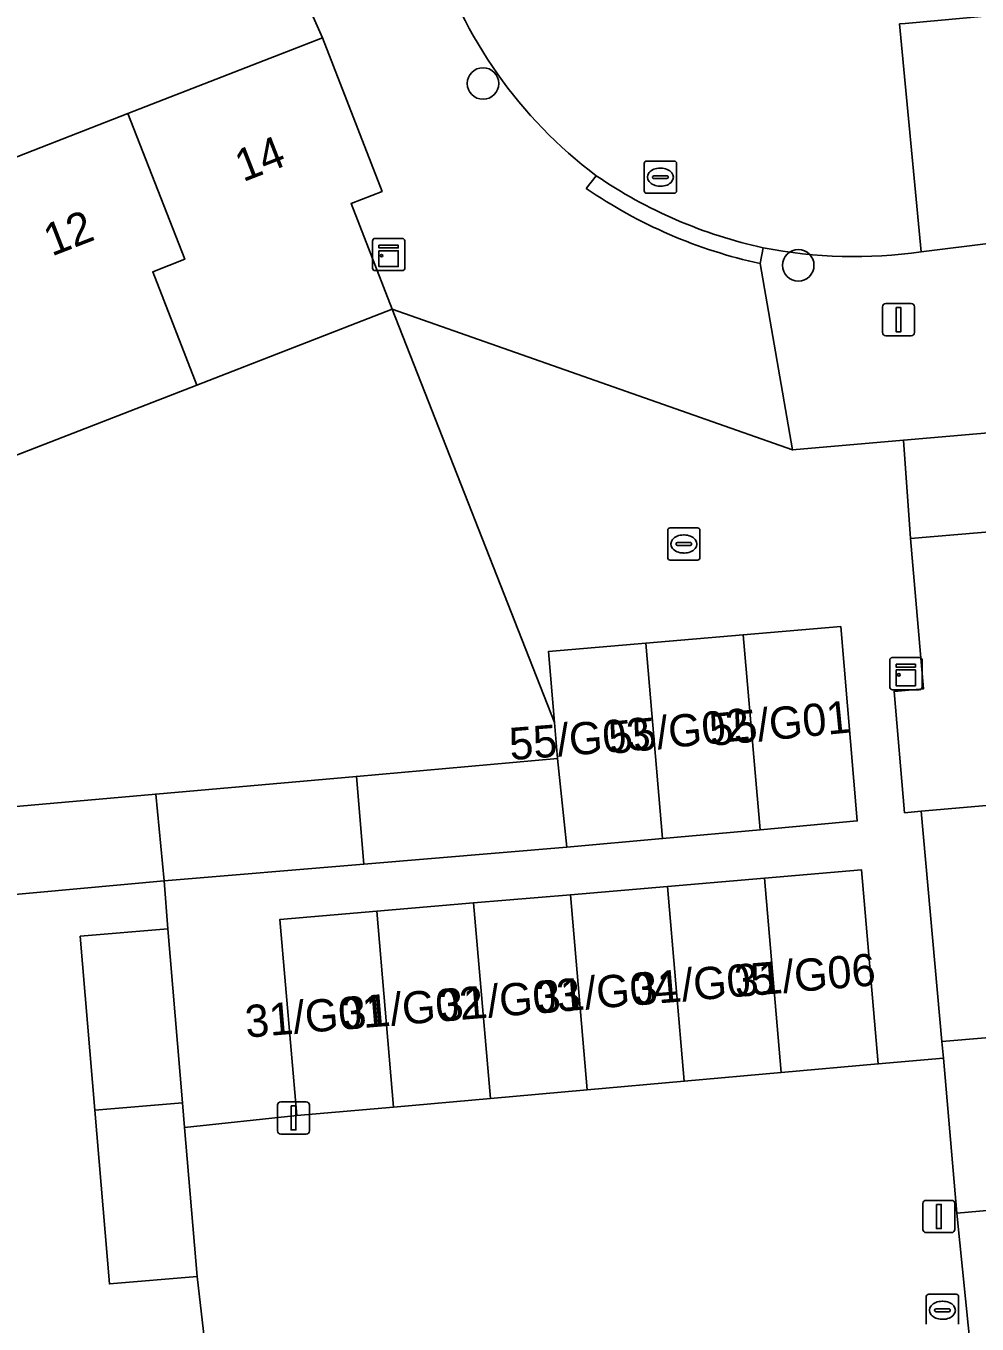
# Model space of a CAD drawing. Extents: x 162989 to 165008, y 383432 to 384338.
# Drawn here: x 164073.05 to 164102.54, y 383799.65 to 383839.91 of the extents above; entities that cross this region are included whole.
import ezdxf

# ---------------------------------------------------------------- set-up
doc = ezdxf.new("R2010")
doc.units = 0
for name, color, linetype in [('IMGEO_Boom', 7, 'Continuous'), ('IMGEO_Erf', 7, 'Continuous'), ('IMGEO_Kast', 7, 'Continuous'), ('IMGEO_Kolk', 7, 'Continuous'), ('IMGEO_Lichtmast', 7, 'Continuous'), ('IMGEO_Pand', 7, 'Continuous'), ('IMGEO_Pand_nummerreeks', 7, 'Continuous'), ('IMGEO_Rijbaan_lokaal_open', 7, 'Continuous'), ('IMGEO_Rioolput', 7, 'Continuous'), ('IMGEO_Voetpad_open', 7, 'Continuous')]:
    doc.layers.add(name, color=color, linetype=linetype)

msp = doc.modelspace()

# ---------------------------------------------------------------- linework, layer by layer
at = {"layer": 'IMGEO_Boom'}
for centre in [(164087.221, 383838.129), (164096.993, 383832.49)]:
    msp.add_circle(centre, 0.489, dxfattribs=at)
at = {"layer": 'IMGEO_Erf'}
for points in [[(164070.323, 383834.908), (164076.212, 383837.198), (164082.241, 383839.542), (164080.985, 383842.386)], [(164071.795, 383815.62), (164077.071, 383816.088), (164083.294, 383816.64), (164089.534, 383817.193), (164089.438, 383818.313), (164084.4, 383831.132), (164078.346, 383828.778), (164072.435, 383826.48)], [(164148.973, 383831.271), (164100.257, 383827.063), (164100.478, 383824.014), (164106.954, 383824.561), (164113.275, 383825.109), (164119.594, 383825.667), (164125.914, 383826.214), (164132.235, 383826.76), (164138.556, 383827.307), (164144.876, 383827.854), (164151.344, 383828.413), (164151.242, 383829.584)], [(164106.755, 383816.072), (164100.802, 383815.557), (164101.449, 383808.414), (164104.025, 383808.637)], [(164075.185, 383806.287), (164074.73, 383811.682), (164077.445, 383811.911), (164077.339, 383813.397), (164072.023, 383812.912)], [(164079.021, 383770.417), (164079.558, 383770.469), (164080.412, 383771.003), (164080.772, 383771.641), (164080.91, 383772.361), (164080.15, 383781.098), (164077.381, 383780.865), (164076.915, 383786.4), (164079.684, 383786.634), (164079.479, 383788.58), (164076.753, 383788.35), (164076.307, 383793.637), (164075.862, 383798.923), (164078.588, 383799.153), (164078.353, 383801.124), (164075.639, 383800.895), (164075.185, 383806.287)]]:
    msp.add_lwpolyline(points, dxfattribs=at)
at = {"layer": 'IMGEO_Kast'}
for p, q in [((164083.796, 383832.4), (164083.796, 383833.241)), ((164083.796, 383833.241), (164083.796, 383832.4)), ((164083.871, 383833.325), (164084.712, 383833.325)), ((164084.712, 383833.325), (164083.871, 383833.325)), ((164084.796, 383833.25), (164084.796, 383832.409)), ((164084.796, 383832.409), (164084.796, 383833.25)), ((164084.721, 383832.325), (164083.88, 383832.325)), ((164083.88, 383832.325), (164084.721, 383832.325)), ((164099.833, 383819.4), (164099.833, 383820.241)), ((164099.833, 383820.241), (164099.833, 383819.4)), ((164099.908, 383820.325), (164100.749, 383820.325)), ((164100.749, 383820.325), (164099.908, 383820.325)), ((164100.833, 383820.25), (164100.833, 383819.409)), ((164100.833, 383819.409), (164100.833, 383820.25)), ((164100.758, 383819.325), (164099.917, 383819.325)), ((164099.917, 383819.325), (164100.758, 383819.325))]:
    msp.add_line(p, q, dxfattribs=at)
for points in [[(164083.991, 383833.115), (164084.591, 383833.115), (164084.591, 383833.03), (164083.991, 383833.03), (164083.991, 383833.115)], [(164083.991, 383832.94), (164084.591, 383832.94), (164084.591, 383832.451), (164083.991, 383832.451), (164083.991, 383832.94)], [(164100.028, 383820.115), (164100.628, 383820.115), (164100.628, 383820.03), (164100.028, 383820.03), (164100.028, 383820.115)], [(164100.028, 383819.94), (164100.628, 383819.94), (164100.628, 383819.451), (164100.028, 383819.451), (164100.028, 383819.94)]]:
    msp.add_lwpolyline(points, dxfattribs=at)
for centre in [(164084.075, 383832.789), (164100.112, 383819.789)]:
    msp.add_circle(centre, 0.0377, dxfattribs=at)
for centre, start, end in [((164083.874, 383833.247), 92.4484, 184.2845), ((164083.874, 383833.247), 92.4484, 184.2845), ((164084.718, 383833.247), 2.4484, 94.2845), ((164084.718, 383833.247), 2.4484, 94.2845), ((164083.874, 383832.403), 182.4484, 274.2845), ((164083.874, 383832.403), 182.4484, 274.2845), ((164084.718, 383832.403), 272.4484, 4.2845), ((164084.718, 383832.403), 272.4484, 4.2845), ((164099.911, 383820.247), 92.4484, 184.2845), ((164099.911, 383820.247), 92.4484, 184.2845), ((164100.755, 383820.247), 2.4484, 94.2845), ((164100.755, 383820.247), 2.4484, 94.2845), ((164099.911, 383819.403), 182.4484, 274.2845), ((164099.911, 383819.403), 182.4484, 274.2845), ((164100.755, 383819.403), 272.4484, 4.2845), ((164100.755, 383819.403), 272.4484, 4.2845)]:
    msp.add_arc(centre, 0.0779, start, end, dxfattribs=at)
at = {"layer": 'IMGEO_Kolk'}
for p, q in [((164092.946, 383823.421), (164092.946, 383824.273)), ((164093.021, 383824.347), (164093.873, 383824.347)), ((164093.947, 383824.273), (164093.947, 383823.421)), ((164093.205, 383823.841), (164093.205, 383823.853)), ((164093.248, 383823.89), (164093.646, 383823.89)), ((164093.434, 383824.127), (164093.459, 383824.127)), ((164093.689, 383823.853), (164093.689, 383823.841)), ((164093.643, 383823.804), (164093.245, 383823.804)), ((164093.457, 383823.567), (164093.432, 383823.567)), ((164093.873, 383823.347), (164093.021, 383823.347)), ((164100.963, 383799.653), (164100.963, 383800.505)), ((164101.038, 383800.579), (164101.89, 383800.579)), ((164101.964, 383800.505), (164101.964, 383799.653)), ((164101.222, 383800.073), (164101.222, 383800.085)), ((164101.265, 383800.122), (164101.663, 383800.122)), ((164101.451, 383800.359), (164101.476, 383800.359)), ((164101.706, 383800.085), (164101.706, 383800.073)), ((164101.66, 383800.036), (164101.262, 383800.036)), ((164101.474, 383799.799), (164101.449, 383799.799))]:
    msp.add_line(p, q, dxfattribs=at)
for points in [[(164092.946, 383823.421), (164092.946, 383824.273)], [(164093.021, 383824.347), (164093.873, 383824.347)], [(164093.947, 383824.273), (164093.947, 383823.421)], [(164093.873, 383823.347), (164093.021, 383823.347)], [(164100.963, 383799.653), (164100.963, 383800.505)], [(164101.038, 383800.579), (164101.89, 383800.579)], [(164101.964, 383800.505), (164101.964, 383799.653)]]:
    msp.add_lwpolyline(points, dxfattribs=at)
for centre, radius, start, end in [((164093.023, 383824.271), 0.0765, 91.552, 178.448), ((164093.023, 383824.271), 0.0765, 91.552, 178.448), ((164093.871, 383824.271), 0.0765, 1.552, 88.448), ((164093.871, 383824.271), 0.0765, 1.552, 88.448), ((164093.245, 383823.85), 0.0403, 85.8775, 175.7526), ((164093.242, 383823.84), 0.0366, 178.938, 274.7102), ((164093.646, 383823.847), 0.043, 264.8664, 352.4533), ((164093.65, 383823.852), 0.0386, 1.7309, 96.639), ((164093.023, 383823.423), 0.0765, 181.552, 268.448), ((164093.023, 383823.423), 0.0765, 181.552, 268.448), ((164093.871, 383823.423), 0.0765, 271.552, 358.448), ((164093.871, 383823.423), 0.0765, 271.552, 358.448), ((164101.04, 383800.503), 0.0765, 91.552, 178.448), ((164101.04, 383800.503), 0.0765, 91.552, 178.448), ((164101.888, 383800.503), 0.0765, 1.552, 88.448), ((164101.888, 383800.503), 0.0765, 1.552, 88.448), ((164101.262, 383800.082), 0.0403, 85.8775, 175.7526), ((164101.259, 383800.072), 0.0366, 178.938, 274.7102), ((164101.663, 383800.079), 0.043, 264.8664, 352.4533), ((164101.667, 383800.084), 0.0386, 1.7309, 96.639)]:
    msp.add_arc(centre, radius, start, end, dxfattribs=at)
for centre, major_axis, ratio, start_param, end_param in [((164093.433, 383823.847), (-0.387, 0.002), 0.722429, 4.712389, 7.853982), ((164093.458, 383823.847), (-0.39, 0.002), 0.717154, 1.570796, 4.712389), ((164101.45, 383800.079), (-0.387, 0.002), 0.722429, 4.712389, 7.853982), ((164101.475, 383800.079), (-0.39, 0.002), 0.717154, 1.570796, 4.712389)]:
    msp.add_ellipse(centre, major_axis=major_axis, ratio=ratio, start_param=start_param, end_param=end_param, dxfattribs=at)
at = {"layer": 'IMGEO_Lichtmast'}
for p, q in [((164099.607, 383830.405), (164099.607, 383831.205)), ((164099.607, 383831.205), (164099.607, 383830.405)), ((164099.707, 383831.305), (164100.497, 383831.305)), ((164100.497, 383831.305), (164099.707, 383831.305)), ((164100.597, 383831.205), (164100.597, 383830.405)), ((164100.597, 383830.405), (164100.597, 383831.205)), ((164100.497, 383830.305), (164099.707, 383830.305)), ((164099.707, 383830.305), (164100.497, 383830.305)), ((164080.948, 383806.547), (164081.738, 383806.547)), ((164081.738, 383806.547), (164080.948, 383806.547)), ((164080.848, 383805.647), (164080.848, 383806.447)), ((164080.848, 383806.447), (164080.848, 383805.647)), ((164081.838, 383806.447), (164081.838, 383805.647)), ((164081.838, 383805.647), (164081.838, 383806.447)), ((164081.738, 383805.547), (164080.948, 383805.547)), ((164080.948, 383805.547), (164081.738, 383805.547)), ((164100.858, 383802.589), (164100.858, 383803.389)), ((164100.858, 383803.389), (164100.858, 383802.589)), ((164100.958, 383803.489), (164101.748, 383803.489)), ((164101.748, 383803.489), (164100.958, 383803.489)), ((164101.848, 383803.389), (164101.848, 383802.589)), ((164101.848, 383802.589), (164101.848, 383803.389)), ((164101.748, 383802.489), (164100.958, 383802.489)), ((164100.958, 383802.489), (164101.748, 383802.489))]:
    msp.add_line(p, q, dxfattribs=at)
for points in [[(164100.027, 383831.18), (164100.177, 383831.18), (164100.177, 383830.43), (164100.027, 383830.43), (164100.027, 383831.18)], [(164081.268, 383806.422), (164081.418, 383806.422), (164081.418, 383805.672), (164081.268, 383805.672), (164081.268, 383806.422)], [(164101.278, 383803.364), (164101.428, 383803.364), (164101.428, 383802.614), (164101.278, 383802.614), (164101.278, 383803.364)]]:
    msp.add_lwpolyline(points, dxfattribs=at)
for centre, start, end in [((164099.707, 383831.205), 90, 180), ((164099.707, 383831.205), 90, 180), ((164100.497, 383831.205), 0, 90), ((164100.497, 383831.205), 360, 90), ((164099.707, 383830.405), 180, 270), ((164099.707, 383830.405), 180, 270), ((164100.497, 383830.405), 270, 0), ((164100.497, 383830.405), 270, 0), ((164080.948, 383806.447), 90, 180), ((164080.948, 383806.447), 90, 180), ((164081.738, 383806.447), 0, 90), ((164081.738, 383806.447), 360, 90), ((164080.948, 383805.647), 180, 270), ((164080.948, 383805.647), 180, 270), ((164081.738, 383805.647), 270, 0), ((164081.738, 383805.647), 270, 0), ((164100.958, 383803.389), 90, 180), ((164100.958, 383803.389), 90, 180), ((164101.748, 383803.389), 0, 90), ((164101.748, 383803.389), 360, 90), ((164100.958, 383802.589), 180, 270), ((164100.958, 383802.589), 180, 270), ((164101.748, 383802.589), 270, 0), ((164101.748, 383802.589), 270, 0)]:
    msp.add_arc(centre, 0.1, start, end, dxfattribs=at)
at = {"layer": 'IMGEO_Pand'}
for points in [[(164078.346, 383828.778), (164084.4, 383831.132), (164083.127, 383834.407), (164084.092, 383834.782), (164082.241, 383839.542), (164076.212, 383837.198), (164077.97, 383832.678), (164076.98, 383832.291)], [(164078.346, 383828.778), (164076.98, 383832.291), (164077.97, 383832.678), (164076.212, 383837.198), (164070.323, 383834.908), (164072.081, 383830.387), (164071.069, 383829.992), (164072.435, 383826.48)], [(164106.954, 383824.561), (164100.478, 383824.014), (164100.881, 383819.355), (164099.967, 383819.276), (164100.293, 383815.513), (164100.802, 383815.557), (164106.755, 383816.072), (164106.47, 383819.367), (164107.399, 383819.436)], [(164092.269, 383820.768), (164092.789, 383814.711), (164095.808, 383814.983), (164095.29, 383821.027)], [(164095.808, 383814.983), (164098.825, 383815.256), (164098.31, 383821.286), (164095.29, 383821.027)], [(164089.534, 383817.193), (164089.818, 383814.444), (164092.789, 383814.711), (164092.269, 383820.768), (164089.249, 383820.509), (164089.438, 383818.313)], [(164089.534, 383817.193), (164083.294, 383816.64), (164083.523, 383813.916), (164089.818, 383814.444)], [(164083.523, 383813.916), (164083.294, 383816.64), (164077.071, 383816.088), (164077.339, 383813.397)], [(164077.339, 383813.397), (164077.071, 383816.088), (164071.795, 383815.62), (164072.023, 383812.912)], [(164092.939, 383813.228), (164093.457, 383807.185), (164096.462, 383807.452), (164095.944, 383813.486)], [(164095.944, 383813.486), (164096.462, 383807.452), (164099.476, 383807.72), (164098.95, 383813.744)], [(164089.934, 383812.97), (164086.928, 383812.713), (164087.448, 383806.651), (164090.453, 383806.918)], [(164089.934, 383812.97), (164090.453, 383806.918), (164093.457, 383807.185), (164092.939, 383813.228)], [(164083.923, 383812.455), (164084.443, 383806.384), (164087.448, 383806.651), (164086.928, 383812.713)], [(164083.923, 383812.455), (164080.917, 383812.197), (164081.445, 383806.118), (164084.443, 383806.384)], [(164077.899, 383806.518), (164077.445, 383811.911), (164074.73, 383811.682), (164075.185, 383806.287)], [(164101.449, 383808.414), (164101.493, 383807.9), (164101.909, 383803.094), (164104.485, 383803.316), (164104.431, 383803.941), (164104.025, 383808.637)], [(164077.899, 383806.518), (164075.185, 383806.287), (164075.639, 383800.895), (164078.353, 383801.124), (164077.963, 383805.753)]]:
    msp.add_lwpolyline(points, close=True, dxfattribs=at)
at = {"layer": 'IMGEO_Rijbaan_lokaal_open'}
for points in [[(164104.917, 383840.416), (164100.308, 383839.987), (164100.137, 383839.975), (164100.806, 383832.913), (164103.052, 383833.19), (164103.903, 383833.265), (164105.622, 383833.417)], [(164101.909, 383803.094), (164101.493, 383807.9), (164099.476, 383807.72), (164096.462, 383807.452), (164093.457, 383807.185), (164090.453, 383806.918), (164087.448, 383806.651), (164084.443, 383806.384), (164081.445, 383806.118), (164077.963, 383805.753), (164078.353, 383801.124), (164078.588, 383799.153), (164078.94, 383794.978), (164084.072, 383795.348), (164089.487, 383795.805), (164091.504, 383796.007), (164096.579, 383796.435), (164102.004, 383796.892), (164102.526, 383796.966)]]:
    msp.add_lwpolyline(points, close=True, dxfattribs=at)
for points in [[(164100.806, 383832.913), (164100.137, 383839.975)], [(164104.485, 383803.316), (164101.909, 383803.094), (164102.526, 383796.966), (164103.031, 383797.037)]]:
    msp.add_lwpolyline(points, dxfattribs=at)
for centre, radius, start, end in [((164099.3, 383846.632), 14.233, 197.3719, 232.9842), ((164099.061, 383847.465), 14.771, 235.6702, 257.6818), ((164098.712, 383847.31), 14.549, 258.8945, 278.2741)]:
    msp.add_arc(centre, radius, start, end, dxfattribs=at)
at = {"layer": 'IMGEO_Rioolput'}
for p, q in [((164092.219, 383834.798), (164092.219, 383835.65)), ((164092.294, 383835.724), (164093.146, 383835.724)), ((164092.707, 383835.504), (164092.732, 383835.504)), ((164093.22, 383835.65), (164093.22, 383834.798)), ((164092.478, 383835.218), (164092.478, 383835.23)), ((164092.916, 383835.181), (164092.518, 383835.181)), ((164092.521, 383835.267), (164092.919, 383835.267)), ((164092.962, 383835.23), (164092.962, 383835.218)), ((164093.146, 383834.724), (164092.294, 383834.724)), ((164092.73, 383834.944), (164092.705, 383834.944))]:
    msp.add_line(p, q, dxfattribs=at)
for points in [[(164092.219, 383834.798), (164092.219, 383835.65)], [(164092.294, 383835.724), (164093.146, 383835.724)], [(164093.22, 383835.65), (164093.22, 383834.798)], [(164093.146, 383834.724), (164092.294, 383834.724)]]:
    msp.add_lwpolyline(points, dxfattribs=at)
for centre, radius, start, end in [((164092.296, 383835.648), 0.0765, 91.552, 178.448), ((164092.296, 383835.648), 0.0765, 91.552, 178.448), ((164093.144, 383835.648), 0.0765, 1.552, 88.448), ((164093.144, 383835.648), 0.0765, 1.552, 88.448), ((164092.518, 383835.227), 0.0403, 85.8775, 175.7526), ((164092.515, 383835.217), 0.0366, 178.938, 274.7102), ((164092.919, 383835.224), 0.043, 264.8664, 352.4533), ((164092.923, 383835.229), 0.0386, 1.7309, 96.639), ((164092.296, 383834.8), 0.0765, 181.552, 268.448), ((164092.296, 383834.8), 0.0765, 181.552, 268.448), ((164093.144, 383834.8), 0.0765, 271.552, 358.448), ((164093.144, 383834.8), 0.0765, 271.552, 358.448)]:
    msp.add_arc(centre, radius, start, end, dxfattribs=at)
for centre, major_axis, ratio, start_param, end_param in [((164092.706, 383835.224), (-0.387, 0.002), 0.722429, 4.712389, 7.853982), ((164092.731, 383835.224), (-0.39, 0.002), 0.717154, 1.570796, 4.712389)]:
    msp.add_ellipse(centre, major_axis=major_axis, ratio=ratio, start_param=start_param, end_param=end_param, dxfattribs=at)
at = {"layer": 'IMGEO_Voetpad_open'}
for points in [[(164057.713, 383900.477), (164061.445, 383891.253), (164073.49, 383860.143), (164077.601, 383849.152), (164077.857, 383849.249), (164080.985, 383842.386), (164082.241, 383839.542), (164084.092, 383834.782), (164083.127, 383834.407), (164084.4, 383831.132), (164096.82, 383826.766), (164095.81, 383832.544)], [(164090.731, 383835.267), (164090.421, 383834.874)], [(164090.421, 383834.874), (164090.731, 383835.267)], [(164103.903, 383833.265), (164103.052, 383833.19), (164100.806, 383832.913)], [(164095.91, 383833.034), (164095.81, 383832.544), (164096.82, 383826.766), (164100.257, 383827.063), (164148.973, 383831.271)], [(164095.81, 383832.544), (164095.91, 383833.034)]]:
    msp.add_lwpolyline(points, dxfattribs=at)
msp.add_lwpolyline([(164101.493, 383807.9), (164101.449, 383808.414), (164100.802, 383815.557), (164100.293, 383815.513), (164099.967, 383819.276), (164100.881, 383819.355), (164100.478, 383824.014), (164100.257, 383827.063), (164096.82, 383826.766), (164084.4, 383831.132), (164089.438, 383818.313), (164089.249, 383820.509), (164092.269, 383820.768), (164095.29, 383821.027), (164098.31, 383821.286), (164098.825, 383815.256), (164095.808, 383814.983), (164092.789, 383814.711), (164089.818, 383814.444), (164083.523, 383813.916), (164077.339, 383813.397), (164077.445, 383811.911), (164077.899, 383806.518), (164077.963, 383805.753), (164081.445, 383806.118), (164080.917, 383812.197), (164083.923, 383812.455), (164086.928, 383812.713), (164089.934, 383812.97), (164092.939, 383813.228), (164095.944, 383813.486), (164098.95, 383813.744), (164099.476, 383807.72)], close=True, dxfattribs=at)
for centre, radius, start, end in [((164099.3, 383846.632), 14.233, 197.3719, 232.9842), ((164099.061, 383847.465), 14.771, 235.6702, 257.6818), ((164099.048, 383847.429), 15.233, 235.5074, 257.729), ((164099.048, 383847.429), 15.233, 235.5074, 257.729), ((164098.712, 383847.31), 14.549, 258.8945, 278.2741)]:
    msp.add_arc(centre, radius, start, end, dxfattribs=at)

# ---------------------------------------------------------------- texts
at = {"layer": 'IMGEO_Pand_nummerreeks'}
for s, rotation, p in [('14', 21.2474, (164079.78, 383835.065)), ('12', 21.2474, (164073.848, 383832.759)), ('55/G02', 5.7992, (164091.163, 383817.331)), ('55/G01', 5.5722, (164094.285, 383817.579)), ('55/G03', 4.5022, (164088.07, 383817.14)), ('31/G06', 4.7636, (164095.053, 383809.796)), ('31/G04', 4.7636, (164088.919, 383809.285)), ('31/G05', 4.7636, (164091.925, 383809.535)), ('31/G02', 4.7636, (164082.896, 383808.783)), ('31/G03', 4.7636, (164085.908, 383809.034)), ('31/G01', 4.7636, (164079.884, 383808.532))]:
    msp.add_text(s, height=1, rotation=rotation, dxfattribs=at).set_placement(p)

doc.saveas('drawing.dxf')
